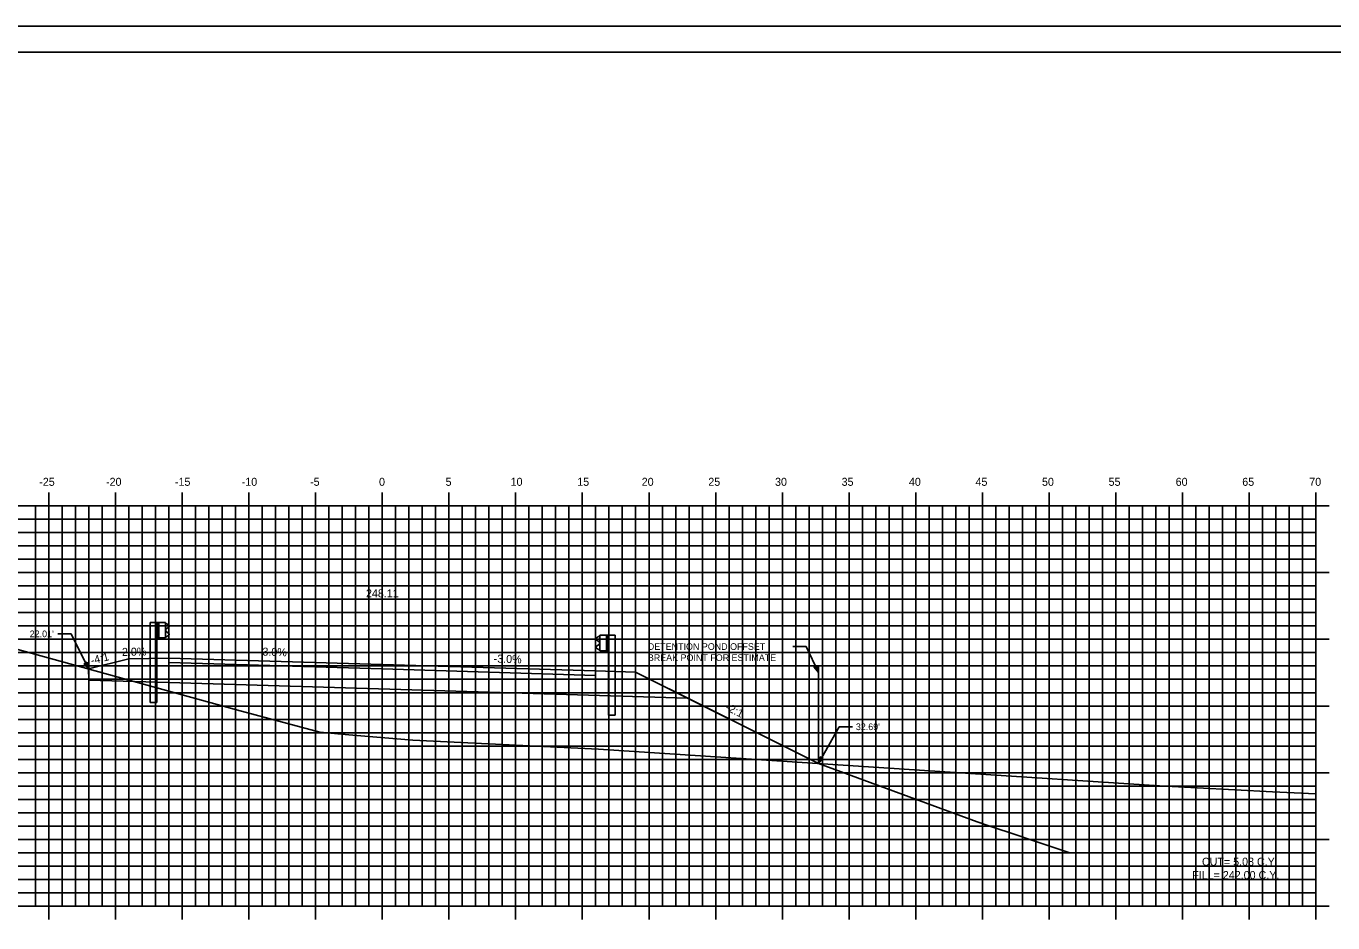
# Model space of a CAD drawing. Extents: x 1170543 to 1177585, y 609599 to 610623.
# Drawn here: x 1172225.8 to 1172323.7, y 609641.6 to 609708.8 of the extents above; entities that cross this region are included whole.
import ezdxf

# ---------------------------------------------------------------- set-up
doc = ezdxf.new("R2010")
doc.units = 0
for name, color, linetype in [('ANNOTATION', 7, 'Continuous'), ('BORDER', 7, 'Continuous'), ('D_Guardrail_Beam_Lt', 7, 'Continuous'), ('D_Guardrail_Beam_Rt', 7, 'Continuous'), ('D_Roadway_Centerline', 7, 'Continuous'), ('D_Roadway_Centerline_Text', 7, 'Continuous'), ('D_Roadway_Edge_Pavement', 7, 'Continuous'), ('D_Roadway_Edge_Shoulder', 7, 'Continuous'), ('D_Roadway_Edge_TW', 7, 'Continuous'), ('D_Roadway_Pavement', 7, 'Continuous'), ('D_Roadway_SlopeLines', 7, 'Continuous'), ('D_Roadway_SubGrade', 7, 'Continuous'), ('H_V ANNOTATION', 7, 'Continuous'), ('MAJOR', 7, 'Continuous'), ('MINOR', 7, 'Continuous'), ('PLOT BOUNDARY', 7, 'Continuous'), ('S_Roadway_Centerline', 7, 'Continuous'), ('SHADING', 7, 'Continuous')]:
    doc.layers.add(name, color=color, linetype=linetype)

msp = doc.modelspace()

# ---------------------------------------------------------------- linework, layer by layer
at = {"layer": 'ANNOTATION'}
for p, q in [((1172228.164, 609663.278), (1172229.164, 609663.278)), ((1172230.467, 609660.651), (1172229.164, 609663.278)), ((1172283.271, 609662.329), (1172284.271, 609662.329)), ((1172285.174, 609660.388), (1172284.271, 609662.329)), ((1172285.174, 609653.565), (1172286.737, 609656.317)), ((1172287.737, 609656.317), (1172286.737, 609656.317))]:
    msp.add_line(p, q, dxfattribs=at)
for points in [[(1172230.357, 609661.154), (1172230.467, 609660.651), (1172230.133, 609661.043)], [(1172285.076, 609660.894), (1172285.174, 609660.388), (1172284.85, 609660.789)], [(1172285.529, 609653.938), (1172285.174, 609653.565), (1172285.312, 609654.062)]]:
    msp.add_lwpolyline(points, close=True, dxfattribs=at)
at = {"layer": 'BORDER'}
msp.add_line((1172337.478, 609706.872), (1172177.478, 609706.872), dxfattribs=at)
at = {"layer": 'D_Guardrail_Beam_Lt'}
for p, q in [((1172235.082, 609664.137), (1172235.082, 609658.137)), ((1172235.553, 609664.137), (1172235.082, 609664.137)), ((1172236.24, 609664.137), (1172235.553, 609664.137)), ((1172235.553, 609664.137), (1172235.553, 609662.97)), ((1172235.615, 609664.137), (1172235.615, 609662.97)), ((1172235.719, 609664.137), (1172235.719, 609662.97)), ((1172236.24, 609662.97), (1172236.24, 609664.137)), ((1172236.24, 609664.054), (1172236.314, 609664.039)), ((1172236.33, 609664.032), (1172236.473, 609663.932)), ((1172236.314, 609663.068), (1172236.24, 609663.054)), ((1172236.244, 609663.589), (1172236.244, 609663.519)), ((1172236.473, 609663.789), (1172236.278, 609663.653)), ((1172236.278, 609663.454), (1172236.473, 609663.318)), ((1172236.473, 609663.175), (1172236.33, 609663.075)), ((1172235.553, 609662.97), (1172236.24, 609662.97)), ((1172235.573, 609658.137), (1172235.573, 609662.97)), ((1172235.573, 609658.137), (1172235.082, 609658.137))]:
    msp.add_line(p, q, dxfattribs=at)
for centre, major_axis, start_param, end_param in [((1172236.306, 609663.998), (0.0417, 0), 0.959931, 1.376053), ((1172236.323, 609663.589), (-0.0789, 0), 5.323254, 6.283185), ((1172236.323, 609663.519), (-0.0789, 0), 6.283185, 7.243116), ((1172236.306, 609663.109), (0.0417, 0), 4.907132, 5.323254), ((1172236.423, 609663.861), (0.0877, 0), 5.323254, 7.243116), ((1172236.423, 609663.246), (0.0877, 0), 5.323254, 7.243116)]:
    msp.add_ellipse(centre, major_axis=major_axis, ratio=0.995501, start_param=start_param, end_param=end_param, dxfattribs=at)
at = {"layer": 'D_Guardrail_Beam_Rt'}
for p, q in [((1172268.691, 609663.072), (1172268.548, 609662.972)), ((1172268.781, 609663.094), (1172268.707, 609663.079)), ((1172268.781, 609663.177), (1172269.469, 609663.177)), ((1172268.781, 609662.01), (1172268.781, 609663.177)), ((1172269.302, 609663.177), (1172269.302, 609662.01)), ((1172269.406, 609663.177), (1172269.406, 609662.01)), ((1172269.469, 609663.177), (1172269.94, 609663.177)), ((1172269.469, 609663.177), (1172269.469, 609662.01)), ((1172269.94, 609663.177), (1172269.94, 609657.177)), ((1172268.548, 609662.829), (1172268.743, 609662.693)), ((1172268.743, 609662.494), (1172268.548, 609662.358)), ((1172268.548, 609662.215), (1172268.691, 609662.115)), ((1172268.707, 609662.108), (1172268.781, 609662.094)), ((1172268.777, 609662.629), (1172268.777, 609662.559)), ((1172269.469, 609662.01), (1172268.781, 609662.01)), ((1172269.448, 609657.177), (1172269.448, 609662.01)), ((1172269.448, 609657.177), (1172269.94, 609657.177))]:
    msp.add_line(p, q, dxfattribs=at)
for centre, major_axis, start_param, end_param in [((1172268.715, 609663.038), (-0.0417, 0), 4.907132, 5.323254), ((1172268.598, 609662.901), (-0.0877, 0), 5.323254, 7.243116), ((1172268.598, 609662.286), (-0.0877, 0), 5.323254, 7.243116), ((1172268.715, 609662.149), (-0.0417, 0), 0.959931, 1.376053), ((1172268.698, 609662.629), (0.0789, 0), 0, 0.959931), ((1172268.698, 609662.559), (0.0789, 0), 5.323254, 6.283185)]:
    msp.add_ellipse(centre, major_axis=major_axis, ratio=0.995501, start_param=start_param, end_param=end_param, dxfattribs=at)
at = {"layer": 'D_Roadway_Centerline'}
msp.add_lwpolyline([(1172230.467, 609660.651), (1172230.467, 609660.651), (1172233.478, 609661.403), (1172236.478, 609661.463), (1172252.478, 609660.983), (1172268.478, 609660.503), (1172271.478, 609660.413), (1172276.442, 609657.931), (1172285.174, 609653.565)], dxfattribs=at)
at = {"layer": 'D_Roadway_Edge_Pavement'}
msp.add_lwpolyline([(1172285.184, 609653.565), (1172297.085, 609649.184), (1172298.019, 609648.872), (1172300.086, 609648.184), (1172301.019, 609647.872), (1172302.086, 609647.517), (1172304.041, 609646.872), (1172313.093, 609646.872), (1172313.704, 609646.872), (1172322.478, 609646.872)], dxfattribs=at)
at = {"layer": 'D_Roadway_Edge_Shoulder'}
for points in [[(1172236.478, 609661.463), (1172236.478, 609661.13)], [(1172268.478, 609660.503), (1172268.478, 609660.17)]]:
    msp.add_lwpolyline(points, dxfattribs=at)
at = {"layer": 'D_Roadway_Edge_TW'}
msp.add_lwpolyline([(1172268.478, 609660.17), (1172268.478, 609660.503), (1172252.478, 609660.983), (1172236.478, 609661.463), (1172236.478, 609661.13), (1172252.478, 609660.65)], close=True, dxfattribs=at)
at = {"layer": 'D_Roadway_Pavement'}
msp.add_line((1172285.174, 609653.565), (1172285.174, 609660.922), dxfattribs=at)
msp.add_lwpolyline([(1172268.478, 609660.17), (1172268.478, 609660.17), (1172252.478, 609660.65), (1172236.478, 609661.13), (1172236.478, 609661.13), (1172252.478, 609660.65)], close=True, dxfattribs=at)
for points in [[(1172236.478, 609661.13), (1172236.478, 609661.13)], [(1172236.478, 609661.13), (1172236.478, 609661.13)], [(1172268.478, 609660.17), (1172268.478, 609660.17)], [(1172268.478, 609660.17), (1172268.478, 609660.17)]]:
    msp.add_lwpolyline(points, dxfattribs=at)
at = {"layer": 'D_Roadway_SlopeLines'}
for points in [[(1172233.478, 609661.403), (1172230.467, 609660.651)], [(1172271.478, 609660.413), (1172285.174, 609653.565)]]:
    msp.add_lwpolyline(points, dxfattribs=at)
at = {"layer": 'D_Roadway_SubGrade'}
for p, q in [((1172230.467, 609660.651), (1172233.478, 609661.403)), ((1172233.478, 609661.403), (1172236.478, 609661.463)), ((1172236.478, 609661.463), (1172236.478, 609659.63)), ((1172252.478, 609660.65), (1172236.478, 609661.13)), ((1172236.478, 609661.13), (1172236.478, 609659.63)), ((1172230.472, 609659.81), (1172230.467, 609660.651)), ((1172268.478, 609660.17), (1172252.478, 609660.65)), ((1172268.478, 609660.503), (1172271.478, 609660.413)), ((1172268.478, 609658.67), (1172268.478, 609660.503)), ((1172268.478, 609658.67), (1172268.478, 609660.17)), ((1172271.478, 609660.413), (1172276.442, 609657.931))]:
    msp.add_line(p, q, dxfattribs=at)
at = {"layer": 'MAJOR'}
for p, q in [((1172227.478, 609673.874), (1172227.478, 609672.872)), ((1172232.478, 609673.874), (1172232.478, 609672.872)), ((1172237.478, 609673.874), (1172237.478, 609672.872)), ((1172242.478, 609673.874), (1172242.478, 609672.872)), ((1172247.478, 609673.874), (1172247.478, 609672.872)), ((1172252.478, 609673.874), (1172252.478, 609672.872)), ((1172257.478, 609673.874), (1172257.478, 609672.872)), ((1172262.478, 609673.874), (1172262.478, 609672.872)), ((1172267.478, 609673.874), (1172267.478, 609672.872)), ((1172272.478, 609673.874), (1172272.478, 609672.872)), ((1172277.478, 609673.874), (1172277.478, 609672.872)), ((1172282.478, 609673.874), (1172282.478, 609672.872)), ((1172287.478, 609673.874), (1172287.478, 609672.872)), ((1172292.478, 609673.874), (1172292.478, 609672.872)), ((1172297.478, 609673.874), (1172297.478, 609672.872)), ((1172302.478, 609673.874), (1172302.478, 609672.872)), ((1172307.478, 609673.874), (1172307.478, 609672.872)), ((1172312.478, 609673.874), (1172312.478, 609672.872)), ((1172317.478, 609673.874), (1172317.478, 609672.872)), ((1172322.478, 609673.874), (1172322.478, 609672.872)), ((1172182.478, 609672.872), (1172322.478, 609672.872)), ((1172182.478, 609672.872), (1172322.478, 609672.872)), ((1172227.478, 609642.872), (1172227.478, 609672.872)), ((1172232.478, 609642.872), (1172232.478, 609672.872)), ((1172237.478, 609642.872), (1172237.478, 609672.872)), ((1172242.478, 609642.872), (1172242.478, 609672.872)), ((1172247.478, 609642.872), (1172247.478, 609672.872)), ((1172252.478, 609642.872), (1172252.478, 609672.872)), ((1172257.478, 609642.872), (1172257.478, 609672.872)), ((1172262.478, 609642.872), (1172262.478, 609672.872)), ((1172267.478, 609642.872), (1172267.478, 609672.872)), ((1172272.478, 609642.872), (1172272.478, 609672.872)), ((1172277.478, 609642.872), (1172277.478, 609672.872)), ((1172282.478, 609642.872), (1172282.478, 609672.872)), ((1172287.478, 609642.872), (1172287.478, 609672.872)), ((1172292.478, 609642.872), (1172292.478, 609672.872)), ((1172297.478, 609642.872), (1172297.478, 609672.872)), ((1172302.478, 609642.872), (1172302.478, 609672.872)), ((1172307.478, 609642.872), (1172307.478, 609672.872)), ((1172312.478, 609642.872), (1172312.478, 609672.872)), ((1172317.478, 609642.872), (1172317.478, 609672.872)), ((1172323.48, 609672.872), (1172321.476, 609672.872)), ((1172322.478, 609642.872), (1172322.478, 609672.872)), ((1172322.478, 609642.872), (1172322.478, 609672.872)), ((1172182.478, 609667.872), (1172322.478, 609667.872)), ((1172323.48, 609667.872), (1172321.476, 609667.872)), ((1172182.478, 609662.872), (1172322.478, 609662.872)), ((1172323.48, 609662.872), (1172321.476, 609662.872)), ((1172182.478, 609657.872), (1172322.478, 609657.872)), ((1172323.48, 609657.872), (1172321.476, 609657.872)), ((1172182.478, 609652.872), (1172322.478, 609652.872)), ((1172323.48, 609652.872), (1172321.476, 609652.872)), ((1172182.478, 609647.872), (1172322.478, 609647.872)), ((1172323.48, 609647.872), (1172321.476, 609647.872)), ((1172182.478, 609642.872), (1172322.478, 609642.872)), ((1172182.478, 609642.872), (1172322.478, 609642.872)), ((1172227.478, 609641.87), (1172227.478, 609642.872)), ((1172232.478, 609641.87), (1172232.478, 609642.872)), ((1172237.478, 609641.87), (1172237.478, 609642.872)), ((1172242.478, 609641.87), (1172242.478, 609642.872)), ((1172247.478, 609641.87), (1172247.478, 609642.872)), ((1172252.478, 609641.87), (1172252.478, 609642.872)), ((1172257.478, 609641.87), (1172257.478, 609642.872)), ((1172262.478, 609641.87), (1172262.478, 609642.872)), ((1172267.478, 609641.87), (1172267.478, 609642.872)), ((1172272.478, 609641.87), (1172272.478, 609642.872)), ((1172277.478, 609641.87), (1172277.478, 609642.872)), ((1172282.478, 609641.87), (1172282.478, 609642.872)), ((1172287.478, 609641.87), (1172287.478, 609642.872)), ((1172292.478, 609641.87), (1172292.478, 609642.872)), ((1172297.478, 609641.87), (1172297.478, 609642.872)), ((1172302.478, 609641.87), (1172302.478, 609642.872)), ((1172307.478, 609641.87), (1172307.478, 609642.872)), ((1172312.478, 609641.87), (1172312.478, 609642.872)), ((1172317.478, 609641.87), (1172317.478, 609642.872)), ((1172323.48, 609642.872), (1172321.476, 609642.872)), ((1172322.478, 609641.87), (1172322.478, 609642.872))]:
    msp.add_line(p, q, dxfattribs=at)
at = {"layer": 'MINOR'}
for p, q in [((1172226.478, 609642.872), (1172226.478, 609672.872)), ((1172228.478, 609642.872), (1172228.478, 609672.872)), ((1172229.478, 609642.872), (1172229.478, 609672.872)), ((1172230.478, 609642.872), (1172230.478, 609672.872)), ((1172231.478, 609642.872), (1172231.478, 609672.872)), ((1172233.478, 609642.872), (1172233.478, 609672.872)), ((1172234.478, 609642.872), (1172234.478, 609672.872)), ((1172235.478, 609642.872), (1172235.478, 609672.872)), ((1172236.478, 609642.872), (1172236.478, 609672.872)), ((1172238.478, 609642.872), (1172238.478, 609672.872)), ((1172239.478, 609642.872), (1172239.478, 609672.872)), ((1172240.478, 609642.872), (1172240.478, 609672.872)), ((1172241.478, 609642.872), (1172241.478, 609672.872)), ((1172243.478, 609642.872), (1172243.478, 609672.872)), ((1172244.478, 609642.872), (1172244.478, 609672.872)), ((1172245.478, 609642.872), (1172245.478, 609672.872)), ((1172246.478, 609642.872), (1172246.478, 609672.872)), ((1172248.478, 609642.872), (1172248.478, 609672.872)), ((1172249.478, 609642.872), (1172249.478, 609672.872)), ((1172250.478, 609642.872), (1172250.478, 609672.872)), ((1172251.478, 609642.872), (1172251.478, 609672.872)), ((1172253.478, 609642.872), (1172253.478, 609672.872)), ((1172254.478, 609642.872), (1172254.478, 609672.872)), ((1172255.478, 609642.872), (1172255.478, 609672.872)), ((1172256.478, 609642.872), (1172256.478, 609672.872)), ((1172258.478, 609642.872), (1172258.478, 609672.872)), ((1172259.478, 609642.872), (1172259.478, 609672.872)), ((1172260.478, 609642.872), (1172260.478, 609672.872)), ((1172261.478, 609642.872), (1172261.478, 609672.872)), ((1172263.478, 609642.872), (1172263.478, 609672.872)), ((1172264.478, 609642.872), (1172264.478, 609672.872)), ((1172265.478, 609642.872), (1172265.478, 609672.872)), ((1172266.478, 609642.872), (1172266.478, 609672.872)), ((1172268.478, 609642.872), (1172268.478, 609672.872)), ((1172269.478, 609642.872), (1172269.478, 609672.872)), ((1172270.478, 609642.872), (1172270.478, 609672.872)), ((1172271.478, 609642.872), (1172271.478, 609672.872)), ((1172273.478, 609642.872), (1172273.478, 609672.872)), ((1172274.478, 609642.872), (1172274.478, 609672.872)), ((1172275.478, 609642.872), (1172275.478, 609672.872)), ((1172276.478, 609642.872), (1172276.478, 609672.872)), ((1172278.478, 609642.872), (1172278.478, 609672.872)), ((1172279.478, 609642.872), (1172279.478, 609672.872)), ((1172280.478, 609642.872), (1172280.478, 609672.872)), ((1172281.478, 609642.872), (1172281.478, 609672.872)), ((1172283.478, 609642.872), (1172283.478, 609672.872)), ((1172284.478, 609642.872), (1172284.478, 609672.872)), ((1172285.478, 609642.872), (1172285.478, 609672.872)), ((1172286.478, 609642.872), (1172286.478, 609672.872)), ((1172288.478, 609642.872), (1172288.478, 609672.872)), ((1172289.478, 609642.872), (1172289.478, 609672.872)), ((1172290.478, 609642.872), (1172290.478, 609672.872)), ((1172291.478, 609642.872), (1172291.478, 609672.872)), ((1172293.478, 609642.872), (1172293.478, 609672.872)), ((1172294.478, 609642.872), (1172294.478, 609672.872)), ((1172295.478, 609642.872), (1172295.478, 609672.872)), ((1172296.478, 609642.872), (1172296.478, 609672.872)), ((1172298.478, 609642.872), (1172298.478, 609672.872)), ((1172299.478, 609642.872), (1172299.478, 609672.872)), ((1172300.478, 609642.872), (1172300.478, 609672.872)), ((1172301.478, 609642.872), (1172301.478, 609672.872)), ((1172303.478, 609642.872), (1172303.478, 609672.872)), ((1172304.478, 609642.872), (1172304.478, 609672.872)), ((1172305.478, 609642.872), (1172305.478, 609672.872)), ((1172306.478, 609642.872), (1172306.478, 609672.872)), ((1172308.478, 609642.872), (1172308.478, 609672.872)), ((1172309.478, 609642.872), (1172309.478, 609672.872)), ((1172310.478, 609642.872), (1172310.478, 609672.872)), ((1172311.478, 609642.872), (1172311.478, 609672.872)), ((1172313.478, 609642.872), (1172313.478, 609672.872)), ((1172314.478, 609642.872), (1172314.478, 609672.872)), ((1172315.478, 609642.872), (1172315.478, 609672.872)), ((1172316.478, 609642.872), (1172316.478, 609672.872)), ((1172318.478, 609642.872), (1172318.478, 609672.872)), ((1172319.478, 609642.872), (1172319.478, 609672.872)), ((1172320.478, 609642.872), (1172320.478, 609672.872)), ((1172321.478, 609642.872), (1172321.478, 609672.872)), ((1172182.478, 609671.872), (1172322.478, 609671.872)), ((1172322.478, 609671.872), (1172321.476, 609671.872)), ((1172182.478, 609670.872), (1172322.478, 609670.872)), ((1172322.478, 609670.872), (1172321.476, 609670.872)), ((1172182.478, 609669.872), (1172322.478, 609669.872)), ((1172322.478, 609669.872), (1172321.476, 609669.872)), ((1172182.478, 609668.872), (1172322.478, 609668.872)), ((1172322.478, 609668.872), (1172321.476, 609668.872)), ((1172182.478, 609666.872), (1172322.478, 609666.872)), ((1172322.478, 609666.872), (1172321.476, 609666.872)), ((1172182.478, 609665.872), (1172322.478, 609665.872)), ((1172322.478, 609665.872), (1172321.476, 609665.872)), ((1172182.478, 609664.872), (1172322.478, 609664.872)), ((1172322.478, 609664.872), (1172321.476, 609664.872)), ((1172182.478, 609663.872), (1172322.478, 609663.872)), ((1172322.478, 609663.872), (1172321.476, 609663.872)), ((1172182.478, 609661.872), (1172322.478, 609661.872)), ((1172322.478, 609661.872), (1172321.476, 609661.872)), ((1172182.478, 609660.872), (1172322.478, 609660.872)), ((1172322.478, 609660.872), (1172321.476, 609660.872)), ((1172182.478, 609659.872), (1172322.478, 609659.872)), ((1172322.478, 609659.872), (1172321.476, 609659.872)), ((1172182.478, 609658.872), (1172322.478, 609658.872)), ((1172322.478, 609658.872), (1172321.476, 609658.872)), ((1172182.478, 609656.872), (1172322.478, 609656.872)), ((1172322.478, 609656.872), (1172321.476, 609656.872)), ((1172182.478, 609655.872), (1172322.478, 609655.872)), ((1172322.478, 609655.872), (1172321.476, 609655.872)), ((1172182.478, 609654.872), (1172322.478, 609654.872)), ((1172322.478, 609654.872), (1172321.476, 609654.872)), ((1172182.478, 609653.872), (1172322.478, 609653.872)), ((1172322.478, 609653.872), (1172321.476, 609653.872)), ((1172182.478, 609651.872), (1172322.478, 609651.872)), ((1172322.478, 609651.872), (1172321.476, 609651.872)), ((1172182.478, 609650.872), (1172322.478, 609650.872)), ((1172322.478, 609650.872), (1172321.476, 609650.872)), ((1172182.478, 609649.872), (1172322.478, 609649.872)), ((1172322.478, 609649.872), (1172321.476, 609649.872)), ((1172182.478, 609648.872), (1172322.478, 609648.872)), ((1172322.478, 609648.872), (1172321.476, 609648.872)), ((1172182.478, 609646.872), (1172322.478, 609646.872)), ((1172322.478, 609646.872), (1172321.476, 609646.872)), ((1172182.478, 609645.872), (1172322.478, 609645.872)), ((1172322.478, 609645.872), (1172321.476, 609645.872)), ((1172182.478, 609644.872), (1172322.478, 609644.872)), ((1172322.478, 609644.872), (1172321.476, 609644.872)), ((1172182.478, 609643.872), (1172322.478, 609643.872)), ((1172322.478, 609643.872), (1172321.476, 609643.872))]:
    msp.add_line(p, q, dxfattribs=at)
at = {"layer": 'PLOT BOUNDARY'}
msp.add_lwpolyline([(1172169.385, 609598.813), (1172339.385, 609598.813), (1172339.385, 609708.813), (1172169.385, 609708.813)], close=True, dxfattribs=at)
at = {"layer": 'S_Roadway_Centerline'}
msp.add_lwpolyline([(1172224.992, 609662.169), (1172241.552, 609657.576), (1172247.794, 609655.907), (1172249.984, 609655.715), (1172254.764, 609655.323), (1172268.681, 609654.639), (1172295.426, 609652.898), (1172310.742, 609651.886), (1172319.216, 609651.442), (1172322.478, 609651.293)], dxfattribs=at)
at = {"layer": 'SHADING'}
msp.add_lwpolyline([(1172230.472, 609659.81), (1172236.474, 609659.63), (1172275.379, 609658.463)], dxfattribs=at)

# ---------------------------------------------------------------- texts
at = {"layer": 'ANNOTATION'}
for s, p in [("22.01'", (1172226.048, 609663.028)), ('DETENTION POND OFFSET', (1172272.391, 609662.079)), ('BREAK POINT FOR ESTIMATE', (1172272.391, 609661.244)), ("32.69'", (1172287.987, 609656.067))]:
    msp.add_text(s, height=0.5, dxfattribs=at).set_placement(p)
for s, rotation, p in [('-2.0%', 1.14576, (1172232.702, 609661.618)), ('3.0%', 358.28164, (1172243.486, 609661.653)), ('-4:1', 14.03624, (1172230.699, 609660.98)), ('-3.0%', 358.28164, (1172260.826, 609661.133)), ('-2:1', 333.43495, (1172278.149, 609657.596))]:
    msp.add_text(s, height=0.6, rotation=rotation, dxfattribs=at).set_placement(p)
at = {"layer": 'D_Roadway_Centerline'}
for s, p in [('C', (1172252.473, 609660.983)), ('L', (1172252.478, 609660.976))]:
    msp.add_text(s, height=0.0146, dxfattribs=at).set_placement(p)
at = {"layer": 'D_Roadway_Centerline_Text'}
for s, p in [('248.11', (1172251.258, 609666.015)), ('CUT= 5.08 C.Y.', (1172313.933, 609645.908)), ('FILL= 242.00 C.Y.', (1172313.205, 609644.906))]:
    msp.add_text(s, height=0.6, dxfattribs=at).set_placement(p)
at = {"layer": 'H_V ANNOTATION'}
for s, p in [('-25', (1172226.763, 609674.372)), ('-20', (1172231.771, 609674.372)), ('-15', (1172236.935, 609674.372)), ('-10', (1172241.943, 609674.372)), ('-5', (1172247.069, 609674.372)), ('0', (1172252.237, 609674.372)), ('5', (1172257.229, 609674.372)), ('10', (1172262.103, 609674.372)), ('15', (1172267.095, 609674.372)), ('20', (1172271.932, 609674.372)), ('25', (1172276.924, 609674.372)), ('30', (1172281.927, 609674.372)), ('35', (1172286.919, 609674.372)), ('40', (1172291.964, 609674.372)), ('45', (1172296.956, 609674.372)), ('50', (1172301.943, 609674.372)), ('55', (1172306.935, 609674.372)), ('60', (1172311.964, 609674.372)), ('65', (1172316.956, 609674.372)), ('70', (1172321.98, 609674.372))]:
    msp.add_text(s, height=0.6, dxfattribs=at).set_placement(p)

doc.saveas('drawing.dxf')
